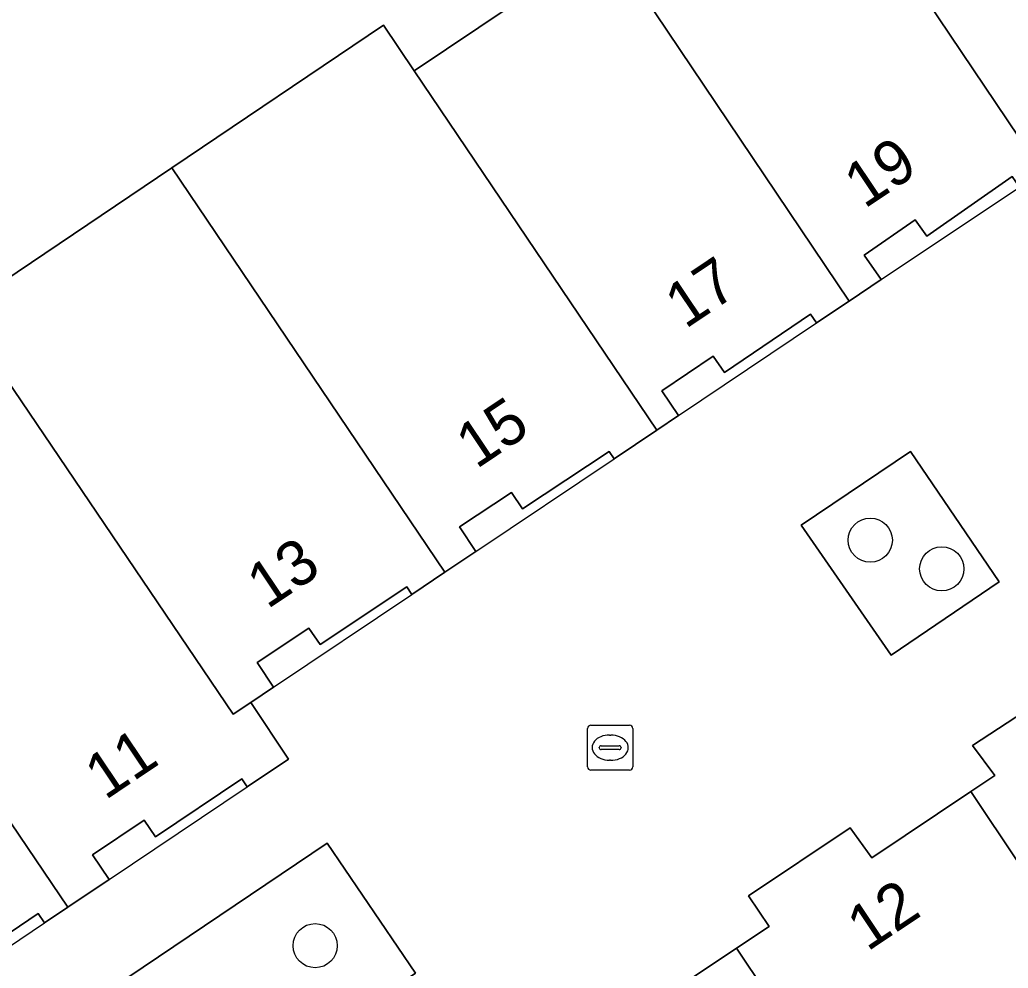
# Model space of a CAD drawing. Extents: x 158793 to 159888, y 384317 to 385256.
# Drawn here: x 159110.93 to 159132.82, y 384807.77 to 384828.77 of the extents above; entities that cross this region are included whole.
import ezdxf

# ---------------------------------------------------------------- set-up
doc = ezdxf.new("R2010")
doc.units = 0
for name, color, linetype in [('IMGEO_Boom', 7, 'Continuous'), ('IMGEO_Erf', 7, 'Continuous'), ('IMGEO_Groenvoorziening', 7, 'Continuous'), ('IMGEO_Kolk', 7, 'Continuous'), ('IMGEO_Pand', 7, 'Continuous'), ('IMGEO_Pand_nummerreeks', 7, 'Continuous'), ('IMGEO_Pand_overbouw', 7, 'Continuous'), ('IMGEO_Voetpad_open', 7, 'Continuous')]:
    doc.layers.add(name, color=color, linetype=linetype)

msp = doc.modelspace()

# ---------------------------------------------------------------- linework, layer by layer
at = {"layer": 'IMGEO_Boom'}
for centre in [(159129.768, 384817.245), (159131.35, 384816.611), (159117.473, 384808.266)]:
    msp.add_circle(centre, 0.489, dxfattribs=at)
at = {"layer": 'IMGEO_Erf'}
msp.add_lwpolyline([(159109.622, 384822.336), (159114.303, 384825.494), (159118.984, 384828.652), (159119.667, 384827.64), (159123.937, 384830.511), (159128.207, 384833.381), (159127.542, 384834.383), (159132.426, 384837.666), (159128.473, 384843.539), (159127.692, 384843.044), (159126.67, 384842.396), (159120.836, 384838.493), (159119.878, 384837.85), (159118.69, 384837.053), (159117.709, 384836.395), (159111.873, 384832.519), (159111.827, 384832.488), (159110.891, 384831.855)], dxfattribs=at)
at = {"layer": 'IMGEO_Groenvoorziening'}
for points in [[(159128.239, 384817.581), (159130.232, 384814.702), (159132.621, 384816.32), (159130.655, 384819.209)], [(159115.289, 384804.676), (159119.696, 384807.657), (159117.741, 384810.533), (159113.323, 384807.564)]]:
    msp.add_lwpolyline(points, close=True, dxfattribs=at)
at = {"layer": 'IMGEO_Kolk'}
for p, q in [((159123.507, 384812.225), (159123.507, 384813.077)), ((159123.582, 384813.151), (159124.434, 384813.151)), ((159124.508, 384813.077), (159124.508, 384812.225)), ((159123.995, 384812.931), (159124.02, 384812.931)), ((159123.766, 384812.645), (159123.766, 384812.657)), ((159124.204, 384812.608), (159123.806, 384812.608)), ((159123.809, 384812.694), (159124.207, 384812.694)), ((159124.25, 384812.657), (159124.25, 384812.645)), ((159124.018, 384812.371), (159123.993, 384812.371)), ((159124.434, 384812.151), (159123.582, 384812.151))]:
    msp.add_line(p, q, dxfattribs=at)
for points in [[(159123.507, 384812.225), (159123.507, 384813.077)], [(159123.582, 384813.151), (159124.434, 384813.151)], [(159124.508, 384813.077), (159124.508, 384812.225)], [(159124.434, 384812.151), (159123.582, 384812.151)]]:
    msp.add_lwpolyline(points, dxfattribs=at)
for centre, radius, start, end in [((159123.584, 384813.075), 0.0765, 91.552, 178.448), ((159123.584, 384813.075), 0.0765, 91.552, 178.448), ((159124.432, 384813.075), 0.0765, 1.552, 88.448), ((159124.432, 384813.075), 0.0765, 1.552, 88.448), ((159123.806, 384812.654), 0.0403, 85.8775, 175.7526), ((159123.803, 384812.644), 0.0366, 178.938, 274.7102), ((159124.207, 384812.651), 0.043, 264.8664, 352.4533), ((159124.211, 384812.656), 0.0386, 1.7309, 96.639), ((159123.584, 384812.227), 0.0765, 181.552, 268.448), ((159123.584, 384812.227), 0.0765, 181.552, 268.448), ((159124.432, 384812.227), 0.0765, 271.552, 358.448), ((159124.432, 384812.227), 0.0765, 271.552, 358.448)]:
    msp.add_arc(centre, radius, start, end, dxfattribs=at)
for centre, major_axis, ratio, start_param, end_param in [((159123.994, 384812.651), (-0.387, 0.002), 0.722429, 4.712389, 7.853982), ((159124.019, 384812.651), (-0.39, 0.002), 0.717154, 1.570796, 4.712389)]:
    msp.add_ellipse(centre, major_axis=major_axis, ratio=ratio, start_param=start_param, end_param=end_param, dxfattribs=at)
at = {"layer": 'IMGEO_Pand'}
for points in [[(159132.426, 384837.666), (159127.542, 384834.383), (159128.207, 384833.381), (159133.576, 384825.406), (159134.485, 384826.016), (159134.121, 384826.552), (159135.262, 384827.327), (159135.51, 384826.964), (159137.416, 384828.259), (159137.546, 384828.069), (159138.469, 384828.688)], [(159128.207, 384833.381), (159123.937, 384830.511), (159129.297, 384822.537), (159130.01, 384823.015), (159129.634, 384823.557), (159130.765, 384824.343), (159131.017, 384823.981), (159132.91, 384825.296), (159133.07, 384825.067), (159133.576, 384825.406)], [(159123.937, 384830.511), (159119.667, 384827.64), (159125.037, 384819.68), (159125.523, 384820.006), (159125.154, 384820.55), (159126.291, 384821.322), (159126.538, 384820.959), (159128.445, 384822.254), (159128.58, 384822.056), (159129.297, 384822.537)], [(159119.667, 384827.64), (159118.984, 384828.652), (159114.303, 384825.494), (159120.347, 384816.535), (159121.035, 384816.997), (159120.672, 384817.543), (159121.819, 384818.304), (159122.063, 384817.938), (159123.984, 384819.213), (159124.093, 384819.048), (159125.037, 384819.68)], [(159114.303, 384825.494), (159109.622, 384822.336), (159110.461, 384821.064), (159115.657, 384813.391), (159116.048, 384813.653), (159116.553, 384813.991), (159116.202, 384814.517), (159116.19, 384814.536), (159117.337, 384815.3), (159117.581, 384814.933), (159119.501, 384816.211), (159119.613, 384816.043), (159120.347, 384816.535)], [(159110.461, 384821.064), (159105.946, 384818.075), (159106.613, 384817.067), (159111.996, 384809.117), (159112.909, 384809.729), (159112.543, 384810.279), (159113.69, 384811.044), (159113.935, 384810.677), (159115.853, 384811.957), (159115.969, 384811.784), (159116.884, 384812.399), (159116.048, 384813.653), (159115.657, 384813.391)], [(159106.613, 384817.067), (159102.574, 384814.354), (159107.957, 384806.404), (159108.42, 384806.715), (159108.04, 384807.273), (159109.181, 384808.049), (159109.429, 384807.685), (159111.336, 384808.981), (159111.48, 384808.77), (159111.996, 384809.117)], [(159140.318, 384810.016), (159136.984, 384815.015), (159134.761, 384813.525), (159134.316, 384814.19), (159132.034, 384812.702), (159132.525, 384812.031), (159131.997, 384811.679), (159137.346, 384803.672), (159142.302, 384807.041)], [(159131.997, 384811.679), (159129.799, 384810.21), (159129.321, 384810.876), (159127.067, 384809.369), (159127.527, 384808.693), (159126.805, 384808.21), (159132.819, 384799.222), (159138.002, 384802.69), (159137.346, 384803.672)], [(159126.805, 384808.21), (159124.782, 384806.858), (159124.338, 384807.53), (159122.083, 384806.017), (159122.528, 384805.353), (159121.559, 384804.704), (159126.971, 384796.732), (159127.635, 384795.754), (159132.819, 384799.222)]]:
    msp.add_lwpolyline(points, close=True, dxfattribs=at)
at = {"layer": 'IMGEO_Pand_overbouw'}
for points in [[(159132.91, 384825.296), (159131.017, 384823.981), (159130.765, 384824.343), (159129.634, 384823.557), (159130.01, 384823.015), (159133.07, 384825.067)], [(159126.538, 384820.959), (159126.291, 384821.322), (159125.154, 384820.55), (159125.523, 384820.006), (159128.58, 384822.056), (159128.445, 384822.254)], [(159122.063, 384817.938), (159121.819, 384818.304), (159120.672, 384817.543), (159121.035, 384816.997), (159124.093, 384819.048), (159123.984, 384819.213)], [(159119.501, 384816.211), (159117.581, 384814.933), (159117.337, 384815.3), (159116.19, 384814.536), (159116.202, 384814.517), (159116.553, 384813.991), (159119.613, 384816.043)], [(159113.935, 384810.677), (159113.69, 384811.044), (159112.543, 384810.279), (159112.909, 384809.729), (159115.969, 384811.784), (159115.853, 384811.957)], [(159111.336, 384808.981), (159109.429, 384807.685), (159109.181, 384808.049), (159108.04, 384807.273), (159108.42, 384806.715), (159111.48, 384808.77)]]:
    msp.add_lwpolyline(points, close=True, dxfattribs=at)
at = {"layer": 'IMGEO_Voetpad_open'}
for points in [[(159132.91, 384825.296), (159131.017, 384823.981), (159130.765, 384824.343), (159129.634, 384823.557), (159130.01, 384823.015), (159129.297, 384822.537), (159128.58, 384822.056), (159128.445, 384822.254), (159126.538, 384820.959), (159126.291, 384821.322), (159125.154, 384820.55), (159125.523, 384820.006), (159125.037, 384819.68), (159124.093, 384819.048), (159123.984, 384819.213), (159122.063, 384817.938), (159121.819, 384818.304), (159120.672, 384817.543), (159121.035, 384816.997), (159120.347, 384816.535), (159119.613, 384816.043), (159119.501, 384816.211), (159117.581, 384814.933), (159117.337, 384815.3), (159116.19, 384814.536), (159116.202, 384814.517), (159116.553, 384813.991), (159116.048, 384813.653), (159116.884, 384812.399), (159115.969, 384811.784), (159115.853, 384811.957), (159113.935, 384810.677), (159113.69, 384811.044), (159112.543, 384810.279), (159112.909, 384809.729), (159111.996, 384809.117), (159111.48, 384808.77), (159111.336, 384808.981), (159109.429, 384807.685)], [(159124.782, 384806.858), (159126.805, 384808.21), (159127.527, 384808.693), (159127.067, 384809.369), (159129.321, 384810.876), (159129.799, 384810.21), (159131.997, 384811.679), (159132.525, 384812.031), (159132.034, 384812.702), (159134.316, 384814.19)]]:
    msp.add_lwpolyline(points, dxfattribs=at)
for points in [[(159128.239, 384817.581), (159130.655, 384819.209), (159132.621, 384816.32), (159130.232, 384814.702)], [(159119.696, 384807.657), (159115.289, 384804.676), (159113.323, 384807.564), (159117.741, 384810.533)]]:
    msp.add_lwpolyline(points, close=True, dxfattribs=at)

# ---------------------------------------------------------------- texts
at = {"layer": 'IMGEO_Pand_nummerreeks'}
for s, rotation, p in [('19', 33.8389, (159129.639, 384824.573)), ('17', 33.8561, (159125.672, 384821.911)), ('15', 33.8503, (159121.043, 384818.809)), ('13', 33.8332, (159116.414, 384815.705)), ('11', 33.9076, (159112.825, 384811.478)), ('12', 33.7644, (159129.702, 384808.124))]:
    msp.add_text(s, height=1, rotation=rotation, dxfattribs=at).set_placement(p)

doc.saveas('drawing.dxf')
